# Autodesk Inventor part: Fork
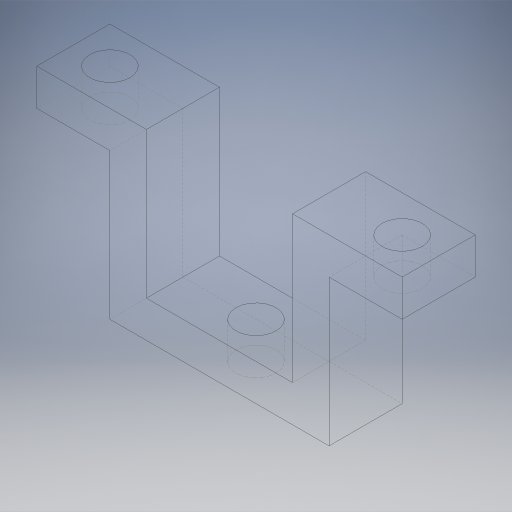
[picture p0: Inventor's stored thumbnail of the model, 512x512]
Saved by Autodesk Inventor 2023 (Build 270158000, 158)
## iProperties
Created: 2024-01
Part Number: Fork
Material: Generic
Document SubType Name: Modeling
Designer: tornqvih
Density: 1 g/cm^3
Appearance: Default
Author: tornqvih
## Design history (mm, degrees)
sketch "Sketch1"
  geometry: L1 (-25, 20)-(-10, 20); L2 (-10, 20)-(-10, 0); L3 (-10, 0)-(10, 0); L4 (10, 0)-(10, 20); L5 (10, 20)-(25, 20); L6 (25, 20)-(25, 15); L7 (25, 15)-(15, 15); L8 (15, 15)-(15, -5); L9 (15, -5)-(-15, -5); L10 (-15, -5)-(-15, 15); L11 (-15, 15)-(-25, 15); L12 (-25, 15)-(-25, 20); L13 (0, -10)-(0, 25) reference; 1 further point
  constraints: 24 end point, 6 symmetric about line, 3 vertical, 2 horizontal, 2 horizontal alignment, 1 midpoint
  dimensions: "d0" = 5 distance of L11.end L1.start; "d1" = 5 distance between parallel lines of L2 L10; "d2" = 5 distance between parallel lines of L9 L3; "d3" = 20 distance of L2.end L3.end; "d5" = 20 distance of L1.end L2.end; "d8" = 10 distance of L10.end L11.end
extrude "Extrusion1" new body sketch "Sketch1" distance "d6" = 10; taper "d7" = 0 deg
sketch "Sketch2"
  geometry: L1 (0, 0)-(30, 0) reference; 3 further points
  constraints: 1 midpoint, 1 vertical alignment
  dimensions: "d9" = 5 distance from line of L1 point (15, 5)
hole "Hole1" sketch "Sketch2" at (15, 5) diameter "d10" = 5.5; stored, may be unused: countersink angle "d14" = 90 deg, drill point angle "d16" = 118 deg; dims "d11" = 10, "d12" = 3.6, "d13" = 4.3, "d15" = 8
sketch "Sketch3"
  geometry: L1 (0, 0)-(10, 0) reference; L2 (0, 0)-(0, 10) reference; L3 (50, 0)-(50, 10) reference; 3 further points
  constraints: 1 horizontal alignment
  dimensions: "d17" = 5 distance from line of L1 point (5, 5); "d18" = 5 distance from line of L2 point (5, 5); "d19" = 5 distance from line of L3 point (45, 5)
hole "Hole2" sketch "Sketch3" at (5, 5), (45, 5) diameter "d20" = 5.5; stored, may be unused: countersink angle "d24" = 90 deg, drill point angle "d26" = 118 deg; dims "d21" = 6, "d22" = 4, "d23" = 2, "d25" = 8
body "Solid1"
